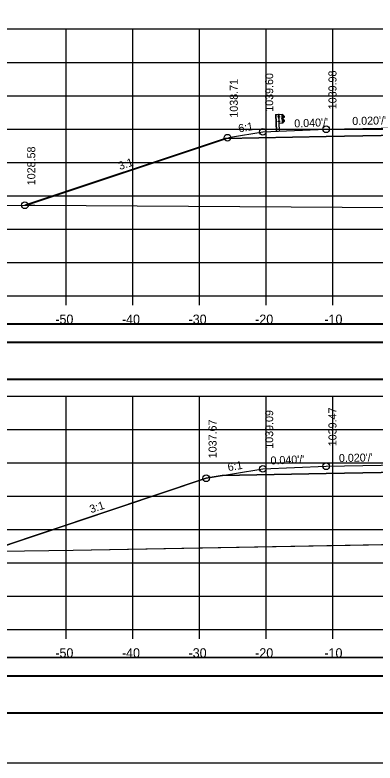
# Model space of a CAD drawing. Extents: x 1370565 to 1374448, y 301010 to 304637.
# Drawn here: x 1373311.1 to 1373365.2, y 302369 to 302481.1 of the extents above; entities that cross this region are included whole.
import ezdxf

# ---------------------------------------------------------------- set-up
doc = ezdxf.new("R2010")
doc.units = 0
for name, color, linetype in [('Default', 7, 'Continuous'), ('R_Alt Surface', 7, 'Continuous'), ('R_Axis', 7, 'Continuous'), ('R_Axis Annot', 7, 'Continuous'), ('R_Border', 7, 'Continuous'), ('R_Contours', 7, 'Continuous'), ('R_Drive', 7, 'Continuous'), ('R_Exist Surface', 7, 'Continuous'), ('R_Fin Surface', 7, 'Continuous'), ('R_Grid', 7, 'Continuous'), ('R_No Plot', 7, 'Continuous'), ('R_Proposed Road', 7, 'Continuous'), ('R_Xsect Elev', 7, 'Continuous'), ('R_Xsect Slope', 7, 'Continuous')]:
    doc.layers.add(name, color=color, linetype=linetype)

# ---------------------------------------------------------------- blocks, each defined once
blk = doc.blocks.new('GUARDRAIL LT_P')
at = {"layer": 'R_Proposed Road'}
for p, q in [((0, 2.52), (0, 0)), ((0.03, 2.52), (0.03, 0)), ((0.53, 2.52), (0.46, 2.51)), ((0.49, 0), (0.49, 2.52)), ((0.53, 2.52), (0.52, 2.52)), ((1.02, 1.15), (1.02, 2.51)), ((1.17, 2.3), (1.06, 2.36)), ((1.16, 2.29), (1.06, 2.34)), ((1.28, 2.18), (1.16, 2.29)), ((1.3, 2.2), (1.17, 2.3)), ((0.39, 1.42), (0.39, 1.51)), ((0.4, 2.11), (0.4, 2.2)), ((0.45, 1.53), (0.4, 1.53)), ((0.45, 1.49), (0.4, 1.49)), ((0.45, 1.43), (0.4, 1.43)), ((0.45, 1.43), (0.4, 1.43)), ((0.45, 1.4), (0.4, 1.4)), ((0.46, 2.21), (0.41, 2.21)), ((0.46, 2.18), (0.41, 2.18)), ((0.46, 2.12), (0.41, 2.12)), ((0.46, 2.12), (0.41, 2.12)), ((0.46, 2.09), (0.41, 2.09)), ((0.45, 1.4), (0.45, 1.53)), ((0.46, 2.09), (0.46, 2.21)), ((0.52, 1.15), (0.49, 1.15)), ((0.58, 2.15), (0.52, 2.15)), ((0.58, 1.46), (0.52, 1.46)), ((0.53, 2.21), (0.58, 2.21)), ((0.53, 2.08), (0.58, 2.08)), ((0.58, 1.53), (0.53, 1.53)), ((0.58, 1.4), (0.53, 1.4)), ((0.58, 2.21), (0.58, 2.08)), ((0.58, 1.4), (0.58, 1.53)), ((1.01, 1.89), (0.96, 1.89)), ((0.96, 1.78), (0.96, 1.88)), ((1.01, 1.86), (0.96, 1.86)), ((1.01, 1.8), (0.96, 1.8)), ((1.01, 1.77), (0.96, 1.77)), ((1.01, 1.8), (0.97, 1.8)), ((1.01, 1.77), (1.01, 1.89)), ((1.05, 1.31), (1.16, 1.37)), ((1.06, 1.77), (1.06, 1.9)), ((1.06, 1.29), (1.17, 1.35)), ((1.09, 1.77), (1.09, 1.9)), ((1.26, 1.6), (1.1, 1.69)), ((1.11, 1.97), (1.28, 2.07)), ((1.12, 1.95), (1.29, 2.05)), ((1.27, 1.62), (1.12, 1.71)), ((1.16, 1.37), (1.29, 1.48)), ((1.17, 1.35), (1.3, 1.46))]:
    blk.add_line(p, q, dxfattribs=at)
blk.add_lwpolyline([(0, 2.52), (0.46, 2.51), (0.45, 0)], dxfattribs=at)
for points in [[(1.05, 2.52), (1.05, 1.15), (0.52, 1.15), (0.53, 2.52)], [(0.39, 1.49), (0.39, 1.43), (0.36, 1.43), (0.36, 1.49)], [(0.4, 2.18), (0.4, 2.12), (0.37, 2.12), (0.37, 2.18)], [(0.44, 1.55), (0.44, 1.38), (0.45, 1.38), (0.45, 1.55)], [(0.45, 2.23), (0.45, 2.07), (0.46, 2.07), (0.46, 2.23)], [(0.58, 2.21), (0.58, 2.08), (0.53, 2.08), (0.53, 2.21)], [(0.58, 1.53), (0.58, 1.4), (0.53, 1.4), (0.53, 1.53)], [(0.95, 1.86), (0.95, 1.8), (0.93, 1.8), (0.93, 1.86)], [(1.01, 1.91), (1.01, 1.75), (1.02, 1.75), (1.02, 1.91)]]:
    blk.add_lwpolyline(points, close=True, dxfattribs=at)
for centre, radius, start, end in [((0.41, 1.51), 0.022, 134.5745, 222.2244), ((0.48, 1.46), 0.0922, 159.7423, 200.2577), ((0.41, 1.41), 0.025, 140.9334, 216.6234), ((0.42, 2.2), 0.022, 134.5745, 222.2244), ((0.49, 2.15), 0.0922, 159.7423, 200.2577), ((0.43, 2.1), 0.025, 140.9334, 216.6234), ((0.98, 1.88), 0.022, 134.5745, 222.2244), ((1.05, 1.83), 0.0922, 159.7423, 200.2577), ((0.98, 1.78), 0.025, 140.9334, 216.6234), ((1.15, 1.89), 0.0865, 118.106, 175.0444), ((1.13, 1.76), 0.0703, 171.7804, 246.8536), ((1.08, 1.83), 0.0453, 282.9554, 86.0697), ((1.15, 1.89), 0.0622, 118.106, 175.0444), ((1.13, 1.76), 0.0462, 171.7804, 246.8536), ((1.22, 1.52), 0.0854, 325.2184, 59.12), ((1.22, 1.52), 0.109, 325.2184, 59.12), ((1.25, 2.13), 0.062, 299.2499, 57.9783), ((1.25, 2.13), 0.0856, 299.2499, 57.9783)]:
    blk.add_arc(centre, radius, start, end, dxfattribs=at)

msp = doc.modelspace()

# ---------------------------------------------------------------- linework, layer by layer
at = {"layer": 'Default'}
for points in [[(1373219.61, 302432.03), (1373518.02, 302432.03), (1373518.02, 302434.73), (1373219.61, 302434.73)], [(1373219.61, 302426.45), (1373518.02, 302426.45), (1373518.02, 302431.97), (1373219.61, 302431.97)], [(1373219.61, 302382.03), (1373518.02, 302382.03), (1373518.02, 302384.73), (1373219.61, 302384.73)], [(1373219.61, 302376.45), (1373518.02, 302376.45), (1373518.02, 302381.97), (1373219.61, 302381.97)]]:
    msp.add_lwpolyline(points, close=True, dxfattribs=at)
at = {"layer": 'R_Alt Surface'}
for points in [[(1373342.64, 302462.58), (1373357.81, 302462.88), (1373368.81, 302463.1), (1373379.81, 302462.88), (1373392.17, 302462.63)], [(1373342.22, 302412.06), (1373357.81, 302412.37), (1373368.81, 302412.59), (1373379.81, 302412.37), (1373395.41, 302412.06)]]:
    msp.add_lwpolyline(points, dxfattribs=at)
at = {"layer": 'R_Axis'}
for p, q in [((1373218.81, 302438.99), (1373518.81, 302438.99)), ((1373318.81, 302437.59), (1373318.81, 302438.99)), ((1373328.81, 302437.59), (1373328.81, 302438.99)), ((1373338.81, 302437.59), (1373338.81, 302438.99)), ((1373348.81, 302437.59), (1373348.81, 302438.99)), ((1373358.81, 302437.59), (1373358.81, 302438.99)), ((1373218.81, 302388.99), (1373518.81, 302388.99)), ((1373318.81, 302387.59), (1373318.81, 302388.99)), ((1373328.81, 302387.59), (1373328.81, 302388.99)), ((1373338.81, 302387.59), (1373338.81, 302388.99)), ((1373348.81, 302387.59), (1373348.81, 302388.99)), ((1373358.81, 302387.59), (1373358.81, 302388.99))]:
    msp.add_line(p, q, dxfattribs=at)
at = {"layer": 'R_Border'}
msp.add_line((1373526.99, 302368.99), (1373210.81, 302368.99), dxfattribs=at)
at = {"layer": 'R_Contours'}
for p, q in [((1373342.64, 302462.58), (1373312.6, 302452.57)), ((1373339.81, 302411.66), (1373307.13, 302400.76)), ((1373342.22, 302412.06), (1373339.81, 302411.66))]:
    msp.add_line(p, q, dxfattribs=at)
for points in [[(1373390.7, 302462.66), (1373379.81, 302462.88), (1373368.81, 302463.1), (1373357.81, 302462.88), (1373342.64, 302462.58)], [(1373312.6, 302452.57), (1373314.08, 302452.57), (1373367.92, 302452.22), (1373368.81, 302452.21), (1373371.67, 302452.19), (1373372.23, 302452.22), (1373384.1, 302453.1), (1373394.14, 302456.51), (1373398, 302457.79)], [(1373390.7, 302412.15), (1373379.81, 302412.37), (1373368.81, 302412.59), (1373357.81, 302412.37), (1373342.22, 302412.06)], [(1373307.13, 302400.76), (1373308.81, 302400.75), (1373319.85, 302400.9), (1373368.81, 302401.77), (1373369.7, 302401.79), (1373382.56, 302402.89), (1373382.74, 302402.94), (1373397.42, 302407.67)]]:
    msp.add_lwpolyline(points, dxfattribs=at)
at = {"layer": 'R_Drive'}
for points in [[(1373219.61, 302432.08), (1373518.02, 302432.08), (1373518.02, 302434.79), (1373219.61, 302434.79)], [(1373219.61, 302426.56), (1373518.02, 302426.56), (1373518.02, 302432.08), (1373219.61, 302432.08)], [(1373219.61, 302382.08), (1373518.02, 302382.08), (1373518.02, 302384.79), (1373219.61, 302384.79)], [(1373219.61, 302376.56), (1373518.02, 302376.56), (1373518.02, 302382.08), (1373219.61, 302382.08)]]:
    msp.add_lwpolyline(points, close=True, dxfattribs=at)
at = {"layer": 'R_Exist Surface'}
for points in [[(1373284.57, 302452.52), (1373314.08, 302452.57), (1373367.92, 302452.22), (1373371.67, 302452.19), (1373372.23, 302452.22), (1373384.1, 302453.1), (1373394.14, 302456.51), (1373402.22, 302459.2), (1373410.34, 302459.34), (1373412.27, 302459.38), (1373414.4, 302459.37), (1373423.14, 302459.3), (1373437.81, 302455), (1373443.52, 302453.26), (1373445.63, 302453.26), (1373462.55, 302453.12), (1373467.44, 302453.08), (1373501.45, 302453.5), (1373511.16, 302453.77), (1373518.81, 302453.93)], [(1373308.81, 302400.75), (1373319.85, 302400.9), (1373369.7, 302401.79), (1373382.56, 302402.89), (1373382.61, 302402.89), (1373382.74, 302402.94), (1373402.21, 302409.22), (1373404.69, 302409.25), (1373411.66, 302409.34), (1373414.59, 302409.33), (1373422.42, 302409.27), (1373448.15, 302403.37), (1373448.15, 302403.37), (1373448.15, 302403.37), (1373465.16, 302403.37), (1373478.65, 302403.31), (1373505.68, 302403.16), (1373508.65, 302403.36), (1373513.96, 302403.44), (1373518.81, 302403.44)]]:
    msp.add_lwpolyline(points, dxfattribs=at)
at = {"layer": 'R_Fin Surface'}
for points in [[(1373312.82, 302452.57), (1373343.43, 302462.77), (1373348.31, 302463.58), (1373357.81, 302463.96), (1373368.81, 302464.18), (1373379.81, 302463.96), (1373389.31, 302463.58), (1373402.46, 302459.2), (1373417.26, 302454.27), (1373441.81, 302453.78)], [(1373307.13, 302400.76), (1373339.81, 302411.66), (1373348.31, 302413.08), (1373357.81, 302413.46), (1373368.81, 302413.68), (1373379.81, 302413.46), (1373389.31, 302413.08), (1373397.81, 302411.66), (1373418.52, 302404.76), (1373444.35, 302404.24)]]:
    msp.add_lwpolyline(points, dxfattribs=at)
at = {"layer": 'R_Grid'}
for p, q in [((1373218.81, 302478.99), (1373518.81, 302478.99)), ((1373318.81, 302438.99), (1373318.81, 302478.99)), ((1373328.81, 302438.99), (1373328.81, 302478.99)), ((1373338.81, 302438.99), (1373338.81, 302478.99)), ((1373348.81, 302438.99), (1373348.81, 302478.99)), ((1373358.81, 302438.99), (1373358.81, 302478.99)), ((1373218.81, 302473.99), (1373518.81, 302473.99)), ((1373218.81, 302468.99), (1373518.81, 302468.99)), ((1373218.81, 302463.99), (1373518.81, 302463.99)), ((1373218.81, 302458.99), (1373518.81, 302458.99)), ((1373218.81, 302453.99), (1373518.81, 302453.99)), ((1373218.81, 302448.99), (1373518.81, 302448.99)), ((1373218.81, 302443.99), (1373518.81, 302443.99)), ((1373218.81, 302438.99), (1373518.81, 302438.99)), ((1373218.81, 302423.99), (1373518.81, 302423.99)), ((1373318.81, 302388.99), (1373318.81, 302423.99)), ((1373328.81, 302388.99), (1373328.81, 302423.99)), ((1373338.81, 302388.99), (1373338.81, 302423.99)), ((1373348.81, 302388.99), (1373348.81, 302423.99)), ((1373358.81, 302388.99), (1373358.81, 302423.99)), ((1373218.81, 302418.99), (1373518.81, 302418.99)), ((1373218.81, 302413.99), (1373518.81, 302413.99)), ((1373218.81, 302408.99), (1373518.81, 302408.99)), ((1373218.81, 302403.99), (1373518.81, 302403.99)), ((1373218.81, 302398.99), (1373518.81, 302398.99)), ((1373218.81, 302393.99), (1373518.81, 302393.99)), ((1373218.81, 302388.99), (1373518.81, 302388.99))]:
    msp.add_line(p, q, dxfattribs=at)
at = {"layer": 'R_No Plot'}
msp.add_lwpolyline([(1373444.73, 302574.45), (1373464.35, 302574.45), (1373464.35, 302564.57), (1373480.47, 302564.57), (1373503.67, 302564.57), (1373503.67, 302540.24), (1373526.99, 302540.24), (1373526.99, 302368.99), (1373210.81, 302368.99), (1373210.81, 302574.45)], close=True, dxfattribs=at)
for centre in [(1373357.81, 302463.96), (1373343, 302462.7), (1373348.31, 302463.58), (1373312.6, 302452.57), (1373357.81, 302413.46), (1373348.31, 302413.08), (1373339.81, 302411.66)]:
    msp.add_circle(centre, 0.5, dxfattribs=at)

# ---------------------------------------------------------------- block references
at = {"layer": 'Default', "rotation": 2.3221839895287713}
msp.add_blockref('GUARDRAIL LT_P', (1373350.31, 302463.66), dxfattribs=at)

# ---------------------------------------------------------------- texts
at = {"layer": 'R_Axis Annot'}
for s, p in [('-50', (1373317.16, 302434.79)), ('-40', (1373327.16, 302434.79)), ('-30', (1373337.16, 302434.79)), ('-20', (1373347.16, 302434.79)), ('-10', (1373357.55, 302434.79)), ('-50', (1373317.16, 302384.79)), ('-40', (1373327.16, 302384.79)), ('-30', (1373337.16, 302384.79)), ('-20', (1373347.16, 302384.79)), ('-10', (1373357.55, 302384.79))]:
    msp.add_text(s, height=1.4, dxfattribs=at).set_placement(p)
at = {"layer": 'R_Xsect Elev'}
for s, p in [('1039.60', (1373349.86, 302466.58)), ('1039.98', (1373359.36, 302466.96)), ('1038.71', (1373344.55, 302465.7)), ('1028.58', (1373314.15, 302455.57)), ('1039.09', (1373349.86, 302416.08)), ('1039.47', (1373359.36, 302416.46)), ('1037.67', (1373341.36, 302414.66))]:
    msp.add_text(s, height=1.2, rotation=90, dxfattribs=at).set_placement(p)
at = {"layer": 'R_Xsect Slope'}
for s, rotation, p in [("0.040'/'", 2.2906, (1373353.05, 302464.23)), ("0.020'/'", 1.1458, (1373361.74, 302464.6)), ('6:1', 9.4623, (1373344.73, 302463.49)), ('3:1', 18.4349, (1373326.86, 302457.84)), ("0.040'/'", 2.2906, (1373349.48, 302413.72)), ("0.020'/'", 1.1458, (1373359.74, 302414.09)), ('6:1', 9.4623, (1373343.13, 302412.72)), ('3:1', 18.4349, (1373322.53, 302406.42))]:
    msp.add_text(s, height=1.2, rotation=rotation, dxfattribs=at).set_placement(p)

doc.saveas('drawing.dxf')
